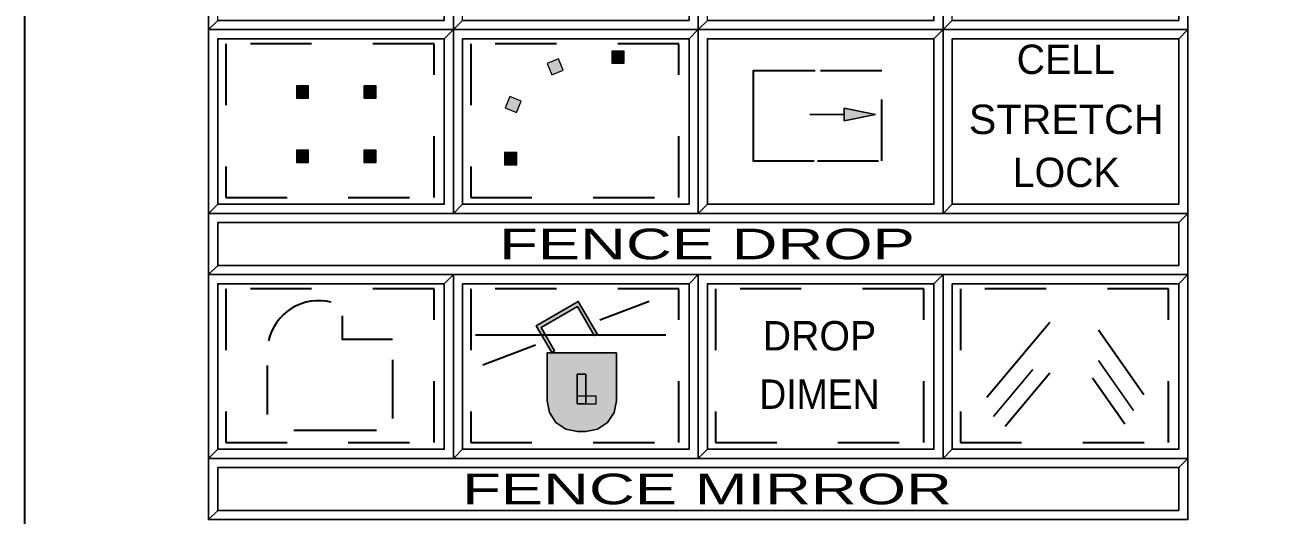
# Model space of a CAD drawing. Extents: x 95906.8 to 95923.6, y 90964.8 to 90972.8.
# Drawn here: x 95906.832 to 95908.871, y 90966.169 to 90966.969 of the extents above; entities that cross this region are included whole.
import ezdxf
from ezdxf.enums import TextEntityAlignment as Align

# ---------------------------------------------------------------- set-up
doc = ezdxf.new("R2010")
doc.units = 0
doc.header["$LTSCALE"] = 0.019
doc.linetypes.add('DOT_DASHED', pattern=[7.7, 5, -1.2, 0.3, -1.2])
doc.linetypes.add('DOTTED', pattern=[1.5, 0.3, -1.2])
for name, color, linetype, lineweight in [('1', 7, 'Continuous', 25), ('11', 7, 'Continuous', 25), ('12', 7, 'Continuous', 25), ('18', 7, 'Continuous', 25), ('2', 7, 'Continuous', 13), ('3', 7, 'Continuous', 25), ('6', 7, 'Continuous', 35), ('7', 7, 'Continuous', 35)]:
    doc.layers.add(name, color=color, linetype=linetype, lineweight=lineweight)

msp = doc.modelspace()

# ---------------------------------------------------------------- hatches: boundary and pattern name
at = {"layer": '6'}
for points in [[(95907.7912, 90966.9067), (95907.8112, 90966.9067), (95907.8112, 90966.9267), (95907.7912, 90966.9267)], [(95907.7115, 90966.8955), (95907.7038, 90966.914), (95907.6854, 90966.9063), (95907.693, 90966.8878)], [(95907.2757, 90966.8499), (95907.2957, 90966.8499), (95907.2957, 90966.8699), (95907.2757, 90966.8699)], [(95907.3861, 90966.8499), (95907.4061, 90966.8499), (95907.4061, 90966.8699), (95907.3861, 90966.8699)], [(95907.6432, 90966.845), (95907.6247, 90966.8527), (95907.6171, 90966.8342), (95907.6355, 90966.8265)], [(95908.2221, 90966.823), (95908.1709, 90966.8128), (95908.1709, 90966.8332)], [(95907.2757, 90966.7446), (95907.2957, 90966.7446), (95907.2957, 90966.7646), (95907.2757, 90966.7646)], [(95907.3861, 90966.7446), (95907.4061, 90966.7446), (95907.4061, 90966.7646), (95907.3861, 90966.7646)], [(95907.636, 90966.7408), (95907.636, 90966.7608), (95907.616, 90966.7608), (95907.616, 90966.7408)], [(95907.693, 90966.4345), (95907.6677, 90966.4783), (95907.7363, 90966.5179), (95907.767, 90966.4648), (95907.7623, 90966.4621), (95907.7351, 90966.5095), (95907.6755, 90966.4753), (95907.6975, 90966.4371)], [(95907.6852, 90966.3554), (95907.6852, 90966.4338), (95907.7987, 90966.4338), (95907.7987, 90966.3554), (95907.7949, 90966.3363), (95907.7841, 90966.32), (95907.7678, 90966.3092), (95907.7487, 90966.3054), (95907.7352, 90966.3054), (95907.7161, 90966.3092), (95907.6998, 90966.32), (95907.689, 90966.3363)], [(95907.7342, 90966.3989), (95907.7484, 90966.3989), (95907.7484, 90966.3508), (95907.7342, 90966.3508)], [(95907.7342, 90966.3508), (95907.7655, 90966.3508), (95907.7655, 90966.3633), (95907.7342, 90966.3633)]]:
    msp.add_hatch(color=256, dxfattribs=at).paths.add_polyline_path(points)

# ---------------------------------------------------------------- linework, layer by layer
at = {"layer": '1'}
for points in [[(95907.1323, 90966.9617), (95907.5323, 90966.9617), (95907.5323, 90967.2617), (95907.1323, 90967.2617)], [(95907.5323, 90966.9617), (95907.9323, 90966.9617), (95907.9323, 90967.2617), (95907.5323, 90967.2617)], [(95907.9323, 90966.9617), (95908.3323, 90966.9617), (95908.3323, 90967.2617), (95907.9323, 90967.2617)], [(95908.3323, 90966.9617), (95908.7323, 90966.9617), (95908.7323, 90967.2617), (95908.3323, 90967.2617)], [(95907.1323, 90966.6617), (95907.5323, 90966.6617), (95907.5323, 90966.9617), (95907.1323, 90966.9617)], [(95907.5323, 90966.6617), (95907.9323, 90966.6617), (95907.9323, 90966.9617), (95907.5323, 90966.9617)], [(95907.9323, 90966.6617), (95908.3323, 90966.6617), (95908.3323, 90966.9617), (95907.9323, 90966.9617)], [(95908.3323, 90966.6617), (95908.7323, 90966.6617), (95908.7323, 90966.9617), (95908.3323, 90966.9617)], [(95907.1323, 90966.5617), (95908.7323, 90966.5617), (95908.7323, 90966.6617), (95907.1323, 90966.6617)], [(95907.1323, 90966.2617), (95907.5323, 90966.2617), (95907.5323, 90966.5617), (95907.1323, 90966.5617)], [(95907.5323, 90966.2617), (95907.9323, 90966.2617), (95907.9323, 90966.5617), (95907.5323, 90966.5617)], [(95907.9323, 90966.2617), (95908.3323, 90966.2617), (95908.3323, 90966.5617), (95907.9323, 90966.5617)], [(95908.3323, 90966.2617), (95908.7323, 90966.2617), (95908.7323, 90966.5617), (95908.3323, 90966.5617)], [(95907.1323, 90966.1617), (95908.7323, 90966.1617), (95908.7323, 90966.2617), (95907.1323, 90966.2617)]]:
    msp.add_lwpolyline(points, close=True, dxfattribs=at)
at = {"layer": '11'}
for points in [[(95907.1473, 90966.6767), (95907.5173, 90966.6767), (95907.5173, 90966.9467), (95907.1473, 90966.9467)], [(95907.5473, 90966.6767), (95907.9173, 90966.6767), (95907.9173, 90966.9467), (95907.5473, 90966.9467)], [(95907.9473, 90966.6767), (95908.3173, 90966.6767), (95908.3173, 90966.9467), (95907.9473, 90966.9467)], [(95908.3473, 90966.6767), (95908.7173, 90966.6767), (95908.7173, 90966.9467), (95908.3473, 90966.9467)], [(95907.5473, 90966.2767), (95907.9173, 90966.2767), (95907.9173, 90966.5467), (95907.5473, 90966.5467)], [(95907.9473, 90966.2767), (95908.3173, 90966.2767), (95908.3173, 90966.5467), (95907.9473, 90966.5467)], [(95908.3473, 90966.2767), (95908.7173, 90966.2767), (95908.7173, 90966.5467), (95908.3473, 90966.5467)]]:
    msp.add_lwpolyline(points, close=True, dxfattribs=at)
at = {"layer": '12'}
msp.add_lwpolyline([(95907.1473, 90966.2767), (95907.5173, 90966.2767), (95907.5173, 90966.5467), (95907.1473, 90966.5467)], close=True, dxfattribs=at)
at = {"layer": '18'}
for points in [[(95907.1473, 90966.5767), (95908.7173, 90966.5767), (95908.7173, 90966.6467), (95907.1473, 90966.6467)], [(95907.1473, 90966.1767), (95908.7173, 90966.1767), (95908.7173, 90966.2467), (95907.1473, 90966.2467)]]:
    msp.add_lwpolyline(points, close=True, dxfattribs=at)
at = {"layer": '2'}
for points in [[(95907.1323, 90967.2617), (95907.1323, 90966.9617), (95907.1473, 90966.9767), (95907.1473, 90967.2467), (95907.5173, 90967.2467), (95907.5323, 90967.2617)], [(95907.5323, 90967.2617), (95907.5323, 90966.9617), (95907.5473, 90966.9767), (95907.5473, 90967.2467), (95907.9173, 90967.2467), (95907.9323, 90967.2617)], [(95907.9323, 90967.2617), (95907.9323, 90966.9617), (95907.9473, 90966.9767), (95907.9473, 90967.2467), (95908.3173, 90967.2467), (95908.3323, 90967.2617)], [(95908.3323, 90967.2617), (95908.3323, 90966.9617), (95908.3473, 90966.9767), (95908.3473, 90967.2467), (95908.7173, 90967.2467), (95908.7323, 90967.2617)], [(95907.1323, 90966.9617), (95907.1323, 90966.6617), (95907.1473, 90966.6767), (95907.1473, 90966.9467), (95907.5173, 90966.9467), (95907.5323, 90966.9617)], [(95907.5323, 90966.9617), (95907.5323, 90966.6617), (95907.5473, 90966.6767), (95907.5473, 90966.9467), (95907.9173, 90966.9467), (95907.9323, 90966.9617)], [(95907.9323, 90966.9617), (95907.9323, 90966.6617), (95907.9473, 90966.6767), (95907.9473, 90966.9467), (95908.3173, 90966.9467), (95908.3323, 90966.9617)], [(95908.3323, 90966.9617), (95908.3323, 90966.6617), (95908.3473, 90966.6767), (95908.3473, 90966.9467), (95908.7173, 90966.9467), (95908.7323, 90966.9617)], [(95907.1323, 90966.6617), (95907.1323, 90966.5617), (95907.1473, 90966.5767), (95907.1473, 90966.6467), (95908.7173, 90966.6467), (95908.7323, 90966.6617)], [(95907.1323, 90966.5617), (95907.1323, 90966.2617), (95907.1473, 90966.2767), (95907.1473, 90966.5467), (95907.5173, 90966.5467), (95907.5323, 90966.5617)], [(95907.5323, 90966.5617), (95907.5323, 90966.2617), (95907.5473, 90966.2767), (95907.5473, 90966.5467), (95907.9173, 90966.5467), (95907.9323, 90966.5617)], [(95907.9323, 90966.5617), (95907.9323, 90966.2617), (95907.9473, 90966.2767), (95907.9473, 90966.5467), (95908.3173, 90966.5467), (95908.3323, 90966.5617)], [(95908.3323, 90966.5617), (95908.3323, 90966.2617), (95908.3473, 90966.2767), (95908.3473, 90966.5467), (95908.7173, 90966.5467), (95908.7323, 90966.5617)], [(95907.1323, 90966.2617), (95907.1323, 90966.1617), (95907.1473, 90966.1767), (95907.1473, 90966.2467), (95908.7173, 90966.2467), (95908.7323, 90966.2617)]]:
    msp.add_lwpolyline(points, close=True, dxfattribs=at)
at = {"layer": '3'}
for points in [[(95907.1323, 90966.9617), (95907.5323, 90966.9617), (95907.5323, 90967.2617), (95907.5173, 90967.2467), (95907.5173, 90966.9767), (95907.1473, 90966.9767)], [(95907.5323, 90966.9617), (95907.9323, 90966.9617), (95907.9323, 90967.2617), (95907.9173, 90967.2467), (95907.9173, 90966.9767), (95907.5473, 90966.9767)], [(95907.9323, 90966.9617), (95908.3323, 90966.9617), (95908.3323, 90967.2617), (95908.3173, 90967.2467), (95908.3173, 90966.9767), (95907.9473, 90966.9767)], [(95908.3323, 90966.9617), (95908.7323, 90966.9617), (95908.7323, 90967.2617), (95908.7173, 90967.2467), (95908.7173, 90966.9767), (95908.3473, 90966.9767)], [(95907.1323, 90966.6617), (95907.5323, 90966.6617), (95907.5323, 90966.9617), (95907.5173, 90966.9467), (95907.5173, 90966.6767), (95907.1473, 90966.6767)], [(95907.5323, 90966.6617), (95907.9323, 90966.6617), (95907.9323, 90966.9617), (95907.9173, 90966.9467), (95907.9173, 90966.6767), (95907.5473, 90966.6767)], [(95907.9323, 90966.6617), (95908.3323, 90966.6617), (95908.3323, 90966.9617), (95908.3173, 90966.9467), (95908.3173, 90966.6767), (95907.9473, 90966.6767)], [(95908.3323, 90966.6617), (95908.7323, 90966.6617), (95908.7323, 90966.9617), (95908.7173, 90966.9467), (95908.7173, 90966.6767), (95908.3473, 90966.6767)], [(95907.1323, 90966.5617), (95908.7323, 90966.5617), (95908.7323, 90966.6617), (95908.7173, 90966.6467), (95908.7173, 90966.5767), (95907.1473, 90966.5767)], [(95907.1323, 90966.2617), (95907.5323, 90966.2617), (95907.5323, 90966.5617), (95907.5173, 90966.5467), (95907.5173, 90966.2767), (95907.1473, 90966.2767)], [(95907.5323, 90966.2617), (95907.9323, 90966.2617), (95907.9323, 90966.5617), (95907.9173, 90966.5467), (95907.9173, 90966.2767), (95907.5473, 90966.2767)], [(95907.9323, 90966.2617), (95908.3323, 90966.2617), (95908.3323, 90966.5617), (95908.3173, 90966.5467), (95908.3173, 90966.2767), (95907.9473, 90966.2767)], [(95908.3323, 90966.2617), (95908.7323, 90966.2617), (95908.7323, 90966.5617), (95908.7173, 90966.5467), (95908.7173, 90966.2767), (95908.3473, 90966.2767)], [(95907.1323, 90966.1617), (95908.7323, 90966.1617), (95908.7323, 90966.2617), (95908.7173, 90966.2467), (95908.7173, 90966.1767), (95907.1473, 90966.1767)]]:
    msp.add_lwpolyline(points, close=True, dxfattribs=at)
at = {"layer": '6', "lineweight": 25}
msp.add_line((95908.1146, 90966.823), (95908.1709, 90966.823), dxfattribs=at)
at = {"layer": '6'}
for p, q in [((95907.8521, 90966.5178), (95907.7717, 90966.4871)), ((95908.404, 90966.3615), (95908.5067, 90966.4839)), ((95908.5862, 90966.4713), (95908.6601, 90966.3657)), ((95907.5685, 90966.4635), (95907.8792, 90966.4635)), ((95907.5804, 90966.4142), (95907.6662, 90966.4469)), ((95907.2284, 90966.3332), (95907.2284, 90966.4131)), ((95907.4328, 90966.4223), (95907.4328, 90966.327)), ((95908.4335, 90966.3142), (95908.5067, 90966.4015)), ((95908.5763, 90966.3931), (95908.629, 90966.3178)), ((95907.4067, 90966.3071), (95907.2714, 90966.3071))]:
    msp.add_line(p, q, dxfattribs=at)
at = {"layer": '6', "linetype": 'DOT_DASHED', "lineweight": 25}
for p, q in [((95908.4147, 90966.3299), (95908.5067, 90966.4396)), ((95908.5862, 90966.4217), (95908.6491, 90966.3319))]:
    msp.add_line(p, q, dxfattribs=at)
at = {"layer": '6', "linetype": 'DOTTED'}
for points in [[(95907.5007, 90966.9382), (95907.1606, 90966.9382), (95907.1606, 90966.6878), (95907.5007, 90966.6878)], [(95907.9007, 90966.9382), (95907.5606, 90966.9382), (95907.5606, 90966.6878), (95907.9007, 90966.6878)], [(95907.5007, 90966.5382), (95907.1606, 90966.5382), (95907.1606, 90966.2878), (95907.5007, 90966.2878)], [(95907.9007, 90966.5382), (95907.5606, 90966.5382), (95907.5606, 90966.2878), (95907.9007, 90966.2878)], [(95908.3007, 90966.5382), (95907.9606, 90966.5382), (95907.9606, 90966.2878), (95908.3007, 90966.2878)], [(95908.7007, 90966.5382), (95908.3606, 90966.5382), (95908.3606, 90966.2878), (95908.7007, 90966.2878)]]:
    msp.add_lwpolyline(points, close=True, dxfattribs=at)
at = {"layer": '6', "lineweight": 13}
for points in [[(95907.7912, 90966.9067), (95907.8112, 90966.9067), (95907.8112, 90966.9267), (95907.7912, 90966.9267)], [(95907.7115, 90966.8955), (95907.7038, 90966.914), (95907.6854, 90966.9063), (95907.693, 90966.8878)], [(95907.2757, 90966.8499), (95907.2957, 90966.8499), (95907.2957, 90966.8699), (95907.2757, 90966.8699)], [(95907.3861, 90966.8499), (95907.4061, 90966.8499), (95907.4061, 90966.8699), (95907.3861, 90966.8699)], [(95907.6432, 90966.845), (95907.6247, 90966.8527), (95907.6171, 90966.8342), (95907.6355, 90966.8265)], [(95907.2757, 90966.7446), (95907.2957, 90966.7446), (95907.2957, 90966.7646), (95907.2757, 90966.7646)], [(95907.3861, 90966.7446), (95907.4061, 90966.7446), (95907.4061, 90966.7646), (95907.3861, 90966.7646)], [(95907.636, 90966.7408), (95907.636, 90966.7608), (95907.616, 90966.7608), (95907.616, 90966.7408)], [(95907.7342, 90966.3508), (95907.7655, 90966.3508), (95907.7655, 90966.3633), (95907.7342, 90966.3633)]]:
    msp.add_lwpolyline(points, close=True, dxfattribs=at)
at = {"layer": '6'}
for points in [[(95908.1231, 90966.8944), (95908.0219, 90966.8944), (95908.0219, 90966.7474), (95908.1214, 90966.7474)], [(95907.4328, 90966.4557), (95907.3513, 90966.4557), (95907.3513, 90966.4946)]]:
    msp.add_lwpolyline(points, dxfattribs=at)
at = {"layer": '6', "linetype": 'DOTTED'}
msp.add_lwpolyline([(95908.127, 90966.7474), (95908.232, 90966.7474), (95908.232, 90966.8944), (95908.1271, 90966.8944)], dxfattribs=at)
at = {"layer": '6', "lineweight": 25}
for points in [[(95908.2221, 90966.823), (95908.1709, 90966.8128), (95908.1709, 90966.8332)], [(95907.693, 90966.4345), (95907.6677, 90966.4783), (95907.7363, 90966.5179), (95907.767, 90966.4648), (95907.7623, 90966.4621), (95907.7351, 90966.5095), (95907.6755, 90966.4753), (95907.6975, 90966.4371)], [(95907.6852, 90966.3554), (95907.6852, 90966.4338), (95907.7987, 90966.4338), (95907.7987, 90966.3554), (95907.7949, 90966.3363), (95907.7841, 90966.32), (95907.7678, 90966.3092), (95907.7487, 90966.3054), (95907.7352, 90966.3054), (95907.7161, 90966.3092), (95907.6998, 90966.32), (95907.689, 90966.3363)], [(95907.7342, 90966.3989), (95907.7484, 90966.3989), (95907.7484, 90966.3508), (95907.7342, 90966.3508)]]:
    msp.add_lwpolyline(points, close=True, dxfattribs=at)
at = {"layer": '6'}
msp.add_arc((95907.3121, 90966.4354), 0.0838, 75.8303, 167.4043, dxfattribs=at)
at = {"layer": '7'}
msp.add_lwpolyline([(95906.8323, 90972.7617), (95918.8323, 90972.7617), (95918.8323, 90964.7617), (95906.8323, 90964.7617)], close=True, dxfattribs=at)

# ---------------------------------------------------------------- texts
at = {"layer": '6'}
for s, p in [('CELL', (95908.5328, 90966.8892)), ('LOCK', (95908.5335, 90966.7046)), ('DROP', (95908.1303, 90966.4379))]:
    msp.add_text(s, height=0.048, dxfattribs=at).set_placement(p, align=Align.CENTER)
for s, width, p in [('STRETCH', 1.05, (95908.5335, 90966.7912)), ('DIMEN', 0.95, (95908.1303, 90966.3425))]:
    msp.add_text(s, height=0.048, dxfattribs=dict(at, width=width)).set_placement(p, align=Align.CENTER)
at = {"layer": '7', "width": 1.55}
for s, p in [('       FENCE DROP      ', (95907.9322, 90966.5867)), ('      FENCE MIRROR     ', (95907.9322, 90966.1867))]:
    msp.add_text(s, height=0.04999, dxfattribs=at).set_placement(p, align=Align.CENTER)

doc.saveas('drawing.dxf')
